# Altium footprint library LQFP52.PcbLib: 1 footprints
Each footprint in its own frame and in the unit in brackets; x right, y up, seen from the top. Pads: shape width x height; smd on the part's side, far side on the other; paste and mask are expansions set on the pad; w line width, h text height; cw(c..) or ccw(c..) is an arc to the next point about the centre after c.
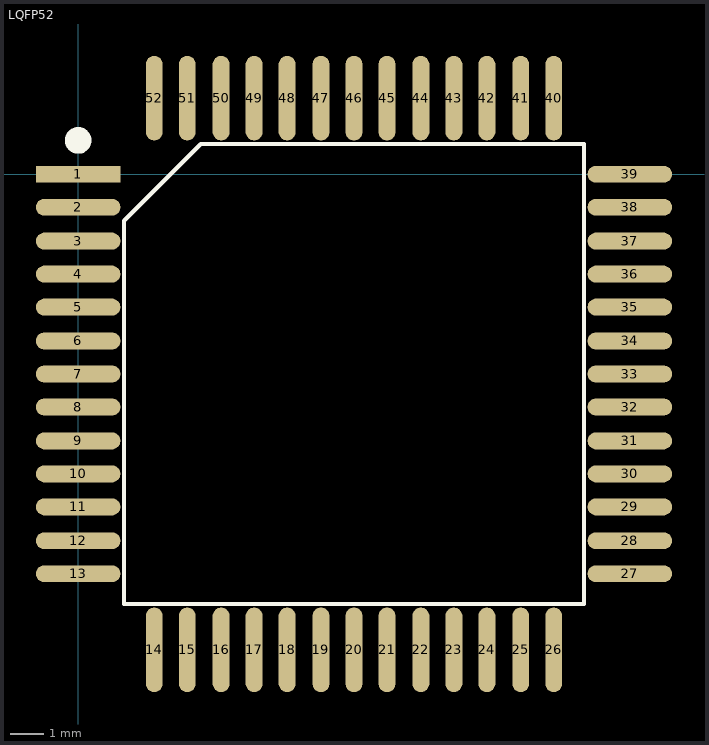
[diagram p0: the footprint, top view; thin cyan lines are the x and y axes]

## LQFP52 [mil]
pads (52):
  rect 100x20 smd: 1(0,0)
  oval 100x20 smd: 2(0,-39) 3(0,-79) 4(0,-118) 5(0,-157) 6(0,-197) 7(0,-236) 8(0,-275) 9(0,-315) 10(0,-354) 11(0,-393) 12(0,-433) 13(0,-472) 27(651.89,-472) 28(651.89,-433) 29(651.89,-393) 30(651.89,-354) 31(651.89,-315) 32(651.89,-275) 33(651.89,-236) 34(651.89,-197) 35(651.89,-157) 36(651.89,-118) 37(651.89,-79) 38(651.89,-39) 39(651.89,0)
  oval 20x100 smd: 14(89.94,-561.94) 15(128.94,-561.94) 16(168.94,-561.94) 17(207.94,-561.94) 18(246.94,-561.94) 19(286.94,-561.94) 20(325.94,-561.94) 21(364.94,-561.94) 22(404.94,-561.94) 23(443.94,-561.94) 24(482.94,-561.94) 25(522.95,-561.94) 26(561.95,-561.94) 40(561.95,89.94) 41(522.95,89.94) 42(482.94,89.94) 43(443.94,89.94) 44(404.94,89.94) 45(364.94,89.94) 46(325.94,89.94) 47(286.94,89.94) 48(246.94,89.94) 49(207.94,89.94) 50(168.94,89.94) 51(128.94,89.94) 52(89.94,89.94)
Top Overlay:
  circle w15.75: c0,40 r7.87
  lines w5: 54.29,-507.65 597.6,-507.65 597.6,35.65 144.84,35.65 54.29,-54.9 54.29,-507.65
